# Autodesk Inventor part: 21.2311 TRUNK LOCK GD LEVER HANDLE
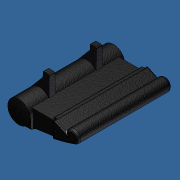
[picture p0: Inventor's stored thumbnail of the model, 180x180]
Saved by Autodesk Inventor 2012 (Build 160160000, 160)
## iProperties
Created: 2014-09
Part Number: 21.2311 TRUNK LOCK GD LEVER HANDLE
Material: AL 6061-T6
Document SubType Name: Modeling
Designer: Admin
Density: 2.7 g/cm^3
Mass: 136.993 g
Surface Area: 126.735 cm^2
Volume: 50.738 cm^3
Author: Admin
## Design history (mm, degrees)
feature "Base1"
body "Solid1"
